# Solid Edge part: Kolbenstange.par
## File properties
Username: ahadarics
Dokumentum tartalom típus: 0
Author: ahadarics
Last saved by: ahadarics
Revision: 78
Sűrűség: 0,000 kg/m^3
Pontosság: 0,990
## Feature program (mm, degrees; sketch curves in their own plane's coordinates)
base feature "unnamed BaseFeature 1"
sketch for "unnamed Protrusion 1" plane through (46.75, 0, 0) normal (1, 0, 0) x-axis (0, 1, 0)
  circle centre (0, 0) radius 5
extrude "unnamed Protrusion 1" add finite 25.5 along -normal
thread "Menet_1"  ThreadDepth = 12 mm
chamfer "Letörés_1" setback 0.4
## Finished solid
Body 1: solid body, 7 faces, 6 edges, 0 vertices.
  Faces by surface: cylinder 3, plane 3, cone 1
  Edges by curve: circle 6
Bounding box of the edges (mm): 113.750 x 10.000 x 10.000, from (-67, -5, -5) to (46.75, 5, 5).
Cylindrical faces by radius (mm): R2 x2, R5 x1
Conical faces (half-angle, radius in mm at the cone's reference point): 45 deg R1.6 x1
Planar faces by outward normal: +x 1, -x 2
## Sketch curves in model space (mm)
circle centre (46.75, 0, 0) radius 5
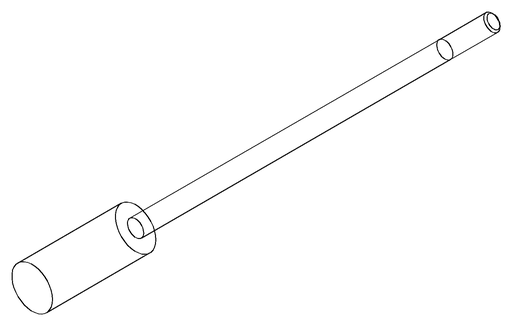
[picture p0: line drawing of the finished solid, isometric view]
